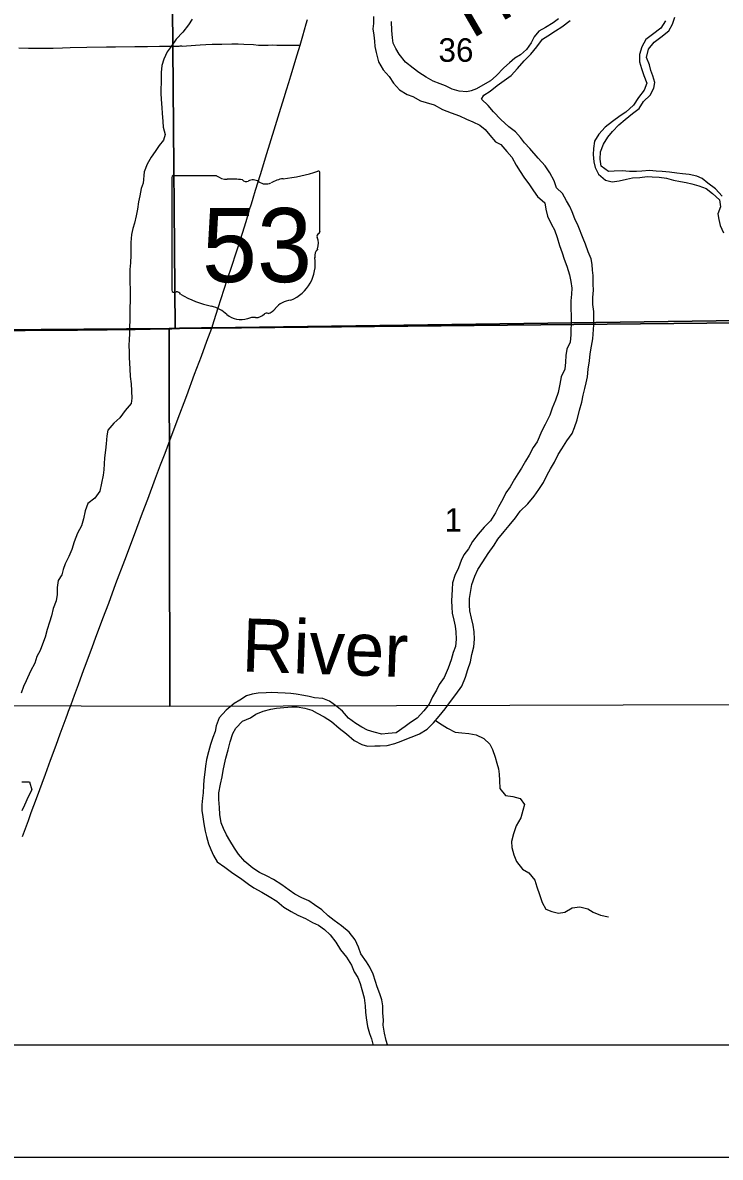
# Model space of a CAD drawing. Extents: x 0 to 34, y 0 to 22.
# Drawn here: x 3.064 to 3.685, y 14 to 15.009 of the extents above; entities that cross this region are included whole.
import ezdxf

# ---------------------------------------------------------------- set-up
doc = ezdxf.new("R2010")
doc.units = 0
for name, color, linetype in [('GM_X_Corporation', 7, 'Continuous'), ('GM_X_County_Road', 7, 'Continuous'), ('GM_X_Major_River', 7, 'Continuous'), ('GM_X_Major_River_Text', 7, 'Continuous'), ('GM_X_Minor_River', 7, 'Continuous'), ('GM_X_Section_Text', 7, 'Continuous'), ('GM_X_State_Location', 7, 'Continuous'), ('GM_X_State_Route', 7, 'Continuous'), ('GM_X_State_Shield', 7, 'Continuous'), ('GM_X_Township_Road', 7, 'Continuous'), ('SH_Data', 7, 'Continuous')]:
    doc.layers.add(name, color=color, linetype=linetype)

msp = doc.modelspace()

# ---------------------------------------------------------------- linework, layer by layer
at = {"layer": 'GM_X_Corporation'}
for points in [[(2.1, 20.7197), (2.1, 14.1), (8.9, 14.1), (8.9, 20.772)], [(3.7029, 14.7443), (3.2322, 14.7378), (3.2232, 14.7378), (3.2036, 14.7375), (3.1968, 14.7374), (3.1775, 14.737), (3.1641, 14.7368), (3.139, 14.7364), (3.1125, 14.7362), (3.0986, 14.7361), (3.0824, 14.736), (3.0715, 14.736), (3.066, 14.7359), (3.0551, 14.7357)], [(3.0551, 14.7357), (3.066, 14.7359), (3.0715, 14.736), (3.0824, 14.736), (3.0986, 14.7361), (3.1125, 14.7362), (3.139, 14.7364), (3.1641, 14.7368), (3.1775, 14.737), (3.1968, 14.7374), (3.2036, 14.7375), (3.2232, 14.7378), (3.2322, 14.7378), (3.7029, 14.7443)], [(2.1, 14.1), (3.6981, 14.1)]]:
    msp.add_lwpolyline(points, dxfattribs=at)
for points in [[(3.1955, 15.238), (3.7037, 15.2451), (3.7028, 14.7423), (3.1999, 14.7374)], [(2.7015, 15.236), (3.1955, 15.238), (3.1999, 14.7374), (3.1944, 14.7372), (2.7002, 14.7334)], [(2.7002, 14.7334), (3.1944, 14.7372), (3.1951, 14.4011), (2.8002, 14.4026), (2.7985, 14.2218), (2.6928, 14.2232), (2.6964, 14.7334)], [(3.1999, 14.7374), (3.7028, 14.7423), (3.6996, 14.4024), (3.1951, 14.4011), (3.1944, 14.7372)]]:
    msp.add_lwpolyline(points, close=True, dxfattribs=at)
at = {"layer": 'GM_X_County_Road'}
msp.add_lwpolyline([(3.0606, 14.9868), (3.0693, 14.9867), (3.0752, 14.9866), (3.0857, 14.9866), (3.0913, 14.9867), (3.0994, 14.9869), (3.1062, 14.9871), (3.1211, 14.9874), (3.1385, 14.9878), (3.1466, 14.9879), (3.164, 14.988), (3.1752, 14.9881), (3.1857, 14.9883), (3.1898, 14.9883), (3.1956, 14.9884), (3.2006, 14.9885), (3.2033, 14.9885), (3.2043, 14.9886), (3.2054, 14.9886), (3.2061, 14.9885), (3.2099, 14.9887), (3.222, 14.9896), (3.2272, 14.9899), (3.2328, 14.9901), (3.2412, 14.9903), (3.2502, 14.9905), (3.2558, 14.9905), (3.2608, 14.9903), (3.2695, 14.9898), (3.2741, 14.9894), (3.2816, 14.9893), (3.2825, 14.9893), (3.2865, 14.9895), (3.2902, 14.9894), (3.2952, 14.9893), (3.2968, 14.9893), (3.3027, 14.9893), (3.3064, 14.9893), (3.3073, 14.9893), (3.311, 14.9892)], dxfattribs=at)
at = {"layer": 'GM_X_Major_River'}
for points in [[(3.3764, 15.0149), (3.3765, 15.0087), (3.3759, 15.0039), (3.3766, 14.9981), (3.3772, 14.9929), (3.3775, 14.9882), (3.3786, 14.9827), (3.3808, 14.9745), (3.385, 14.9674), (3.3902, 14.9615), (3.3942, 14.9556), (3.3994, 14.9495), (3.4064, 14.9455), (3.4113, 14.9435), (3.4181, 14.9397), (3.4233, 14.9383)], [(3.3961, 14.9863), (3.394, 14.9911), (3.3933, 14.9958), (3.3926, 15.0023), (3.3925, 15.0103)], [(3.5411, 15.0126), (3.5363, 15.0092), (3.5296, 15.0051), (3.5235, 15.0017), (3.5195, 14.9968), (3.5168, 14.9915), (3.5126, 14.9853), (3.5072, 14.9808), (3.5023, 14.9778), (3.4975, 14.9736), (3.4925, 14.9691), (3.4857, 14.9621), (3.4805, 14.9576), (3.4757, 14.9548), (3.4681, 14.9505), (3.4634, 14.9488)], [(3.4747, 14.9448), (3.4802, 14.9485), (3.4865, 14.9534), (3.4988, 14.9624), (3.5045, 14.9686), (3.5104, 14.9754), (3.5163, 14.9813), (3.5219, 14.9877), (3.5267, 14.9945), (3.5316, 14.9975), (3.5385, 15.002), (3.544, 15.0057), (3.5515, 15.0113)], [(3.6363, 15.0109), (3.6321, 15.0043), (3.6248, 14.9988), (3.6189, 14.9943), (3.6152, 14.9879), (3.6131, 14.9811), (3.6131, 14.9746), (3.6151, 14.9684), (3.6171, 14.9623), (3.6198, 14.9556), (3.6174, 14.9494), (3.6124, 14.9428), (3.6078, 14.936), (3.601, 14.9298), (3.596, 14.9264), (3.5891, 14.9213), (3.5827, 14.9164), (3.5771, 14.91), (3.5731, 14.904), (3.5721, 14.8975), (3.572, 14.892), (3.5726, 14.8856), (3.5737, 14.8806), (3.5767, 14.8745), (3.5829, 14.8692), (3.5888, 14.8678), (3.5952, 14.8687), (3.6015, 14.8702), (3.607, 14.8713), (3.6134, 14.8716), (3.6199, 14.8725), (3.6246, 14.8723), (3.6307, 14.8719), (3.6372, 14.8709), (3.6434, 14.8693), (3.6498, 14.8681), (3.6548, 14.8671), (3.6599, 14.8658), (3.6661, 14.8642), (3.6724, 14.8617), (3.6782, 14.8573), (3.6843, 14.8517), (3.6854, 14.8455), (3.683, 14.8394), (3.6838, 14.8341), (3.6849, 14.8288), (3.688, 14.8225)], [(3.6869, 14.8549), (3.6807, 14.8614), (3.6739, 14.8666), (3.669, 14.8706), (3.6641, 14.8729), (3.6575, 14.8741), (3.6514, 14.8747), (3.6465, 14.8753), (3.6399, 14.8763), (3.6334, 14.877), (3.6281, 14.8772), (3.6222, 14.8778), (3.6152, 14.8771), (3.6105, 14.8769), (3.6042, 14.877), (3.5976, 14.8774), (3.5905, 14.8771), (3.5856, 14.8768), (3.579, 14.8816), (3.5783, 14.8878), (3.5785, 14.8945), (3.581, 14.9013), (3.5849, 14.9075), (3.5891, 14.9126), (3.5948, 14.9184), (3.6005, 14.9233), (3.6068, 14.9286), (3.6129, 14.9329), (3.6168, 14.9391), (3.6227, 14.9448), (3.626, 14.951), (3.6268, 14.9561), (3.6251, 14.962), (3.6232, 14.9668), (3.622, 14.9717), (3.6195, 14.9784), (3.6213, 14.9858), (3.6263, 14.992), (3.6322, 14.9965), (3.6393, 15.002), (3.6425, 15.008), (3.6447, 15.0141)], [(3.4634, 14.9488), (3.4595, 14.9479), (3.4527, 14.9483), (3.4463, 14.9501), (3.4406, 14.9532), (3.4357, 14.9549), (3.4295, 14.9572), (3.4232, 14.9609), (3.4168, 14.9649), (3.4117, 14.9688), (3.4047, 14.9741), (3.3991, 14.9812), (3.3961, 14.9863)], [(3.3659, 14.3673), (3.3709, 14.3658), (3.3775, 14.3661), (3.3822, 14.3661), (3.3885, 14.3664), (3.3952, 14.3682), (3.4009, 14.3703), (3.4075, 14.3729), (3.4123, 14.3746), (3.4172, 14.3766), (3.4241, 14.3807), (3.4298, 14.3866), (3.4348, 14.3924), (3.4402, 14.3988), (3.4448, 14.4056), (3.4496, 14.4117), (3.4549, 14.4192), (3.4582, 14.427), (3.4602, 14.4338), (3.4627, 14.4408), (3.4639, 14.4472), (3.4656, 14.4542), (3.4662, 14.4609), (3.4659, 14.4675), (3.4652, 14.4734), (3.4637, 14.4795), (3.4622, 14.4861), (3.4617, 14.4912), (3.4618, 14.4971), (3.4626, 14.5024), (3.4639, 14.5094), (3.4665, 14.517), (3.4692, 14.5229), (3.4738, 14.5297), (3.4784, 14.5372), (3.4837, 14.5446), (3.487, 14.55), (3.4927, 14.5568), (3.497, 14.5621), (3.5029, 14.5689), (3.5069, 14.5749), (3.5138, 14.5813), (3.5193, 14.5881), (3.5236, 14.594), (3.5278, 14.6004), (3.5311, 14.6072), (3.5339, 14.6125), (3.5376, 14.6185), (3.5407, 14.6253), (3.5441, 14.6302), (3.5484, 14.6374), (3.5532, 14.644), (3.5553, 14.6493), (3.5576, 14.6561), (3.5598, 14.6645), (3.5619, 14.6717), (3.5629, 14.6779), (3.5646, 14.684), (3.5656, 14.6889), (3.5668, 14.6944), (3.5674, 14.701), (3.5688, 14.7084), (3.5694, 14.7147), (3.5704, 14.7215), (3.5716, 14.7281), (3.5726, 14.7404), (3.5725, 14.7469), (3.5724, 14.7524), (3.5716, 14.7585), (3.5717, 14.7649), (3.5721, 14.7714), (3.572, 14.7767), (3.5718, 14.7843), (3.5713, 14.789), (3.5711, 14.7941), (3.5702, 14.7993), (3.5676, 14.8056), (3.5652, 14.8122), (3.563, 14.8172), (3.5585, 14.8286), (3.5555, 14.8349), (3.5533, 14.841), (3.5512, 14.8457), (3.5482, 14.8507), (3.5445, 14.8573), (3.5394, 14.8625), (3.5373, 14.8686), (3.5334, 14.8756), (3.5291, 14.8821), (3.5231, 14.8888), (3.5154, 14.8974), (3.5108, 14.9024), (3.5073, 14.9073), (3.5028, 14.9123), (3.4967, 14.9167), (3.4896, 14.9232), (3.4833, 14.9299), (3.4783, 14.9356), (3.4726, 14.9412), (3.4747, 14.9448)], [(3.4233, 14.9383), (3.4303, 14.9362), (3.4378, 14.9321), (3.4454, 14.929), (3.453, 14.9263), (3.4592, 14.9234), (3.4649, 14.9211), (3.4709, 14.9182), (3.4758, 14.9142), (3.4798, 14.9092), (3.4849, 14.9033), (3.4898, 14.9008), (3.4952, 14.8947), (3.4996, 14.8897), (3.5033, 14.8825), (3.5069, 14.8768), (3.5102, 14.872), (3.5151, 14.8651), (3.5187, 14.8598), (3.5223, 14.8547), (3.5289, 14.8489), (3.5299, 14.8434), (3.5314, 14.8371), (3.5348, 14.8299), (3.5374, 14.8251), (3.5398, 14.8181), (3.5419, 14.8111), (3.5443, 14.8046), (3.5461, 14.7989), (3.5486, 14.7926), (3.551, 14.785), (3.5519, 14.7791), (3.5528, 14.773), (3.5527, 14.7677), (3.5521, 14.7618), (3.5519, 14.7544), (3.5522, 14.7491), (3.5523, 14.7412), (3.5519, 14.7364), (3.5519, 14.7317), (3.5513, 14.725), (3.5484, 14.719), (3.5476, 14.7133), (3.5474, 14.7074), (3.5466, 14.7012), (3.5433, 14.6942), (3.5421, 14.6876), (3.5407, 14.6804), (3.5384, 14.6735), (3.5355, 14.6665), (3.5332, 14.6601), (3.5291, 14.652), (3.5262, 14.6461), (3.522, 14.6363), (3.5185, 14.6314), (3.5149, 14.6246), (3.5118, 14.6193), (3.508, 14.6129), (3.5049, 14.608), (3.502, 14.6031), (3.498, 14.5963), (3.4943, 14.591), (3.4916, 14.5855), (3.4876, 14.5787), (3.4851, 14.5732), (3.4805, 14.5662), (3.4749, 14.5604), (3.4696, 14.5544), (3.4644, 14.5479), (3.4608, 14.5413), (3.4569, 14.5359), (3.4544, 14.5308), (3.4521, 14.5243), (3.4488, 14.5175), (3.4467, 14.5111), (3.4464, 14.505), (3.4462, 14.5001), (3.4458, 14.495), (3.4461, 14.4893), (3.4465, 14.4841), (3.448, 14.4779), (3.4491, 14.4726), (3.4498, 14.4674), (3.4501, 14.4608), (3.4493, 14.4543), (3.4474, 14.4489), (3.4454, 14.4426), (3.4429, 14.4352), (3.4394, 14.4267), (3.4348, 14.4207), (3.4325, 14.4156), (3.429, 14.4095), (3.4258, 14.4031), (3.4212, 14.3971), (3.4152, 14.3907), (3.4093, 14.3867), (3.4044, 14.3832), (3.3964, 14.3777), (3.3893, 14.377), (3.3838, 14.3765), (3.3768, 14.3781)], [(3.3768, 14.3781), (3.371, 14.38), (3.366, 14.3827), (3.3606, 14.3858), (3.354, 14.3907), (3.3487, 14.397), (3.3438, 14.4009), (3.3372, 14.4057), (3.3311, 14.408), (3.3239, 14.4088), (3.319, 14.41), (3.3143, 14.4108), (3.3074, 14.412), (3.3027, 14.4126), (3.2978, 14.413), (3.2913, 14.4132), (3.2855, 14.4136), (3.2807, 14.4131), (3.2737, 14.4128), (3.2682, 14.4119), (3.2634, 14.4106), (3.2573, 14.4066), (3.2524, 14.4037), (3.2453, 14.3978), (3.239, 14.3909), (3.2363, 14.3839), (3.2353, 14.3789), (3.2334, 14.3733), (3.2312, 14.3672), (3.2295, 14.3608), (3.2277, 14.3539), (3.2269, 14.3479), (3.2261, 14.3426), (3.2253, 14.3358), (3.2251, 14.3306), (3.2248, 14.3242), (3.2242, 14.3194), (3.2236, 14.3136), (3.2236, 14.3085), (3.2245, 14.3029), (3.2254, 14.2967), (3.2265, 14.2902), (3.2276, 14.2853), (3.2294, 14.2788), (3.2315, 14.2737), (3.2339, 14.2685), (3.2373, 14.2628), (3.2439, 14.258), (3.2512, 14.2527), (3.2579, 14.2484), (3.265, 14.2429), (3.2699, 14.2396), (3.2769, 14.236), (3.2835, 14.2321), (3.2903, 14.2279), (3.2966, 14.2224), (3.303, 14.2187), (3.309, 14.2154), (3.3158, 14.2123), (3.3221, 14.2089), (3.3274, 14.2064), (3.3328, 14.2025), (3.3379, 14.1978), (3.3428, 14.1913), (3.3469, 14.1846), (3.3522, 14.1779), (3.3567, 14.1709), (3.3591, 14.165), (3.3623, 14.16), (3.3644, 14.1545), (3.366, 14.1494), (3.3679, 14.142), (3.3688, 14.1347), (3.3693, 14.1292), (3.3698, 14.1241), (3.3711, 14.1163), (3.3729, 14.1102), (3.3746, 14.1055), (3.3757, 14.1005), (3.3758, 14.1)], [(3.3887, 14.1), (3.3877, 14.1039), (3.3862, 14.1103), (3.3851, 14.1174), (3.3852, 14.1221), (3.3848, 14.1285), (3.3847, 14.1346), (3.3838, 14.1401), (3.3819, 14.1453), (3.3795, 14.1517), (3.3782, 14.1565), (3.3762, 14.1629), (3.373, 14.1692), (3.3702, 14.174), (3.3651, 14.1809), (3.3629, 14.1869), (3.3599, 14.1934), (3.3546, 14.2003), (3.348, 14.206), (3.3412, 14.2106), (3.336, 14.2147), (3.3303, 14.2202), (3.3239, 14.2246), (3.3188, 14.2281), (3.3126, 14.2308), (3.3063, 14.2342), (3.3012, 14.2377), (3.2946, 14.2423), (3.2874, 14.2471), (3.2818, 14.2502), (3.2748, 14.2534), (3.2689, 14.2571), (3.2619, 14.2632), (3.2561, 14.2697), (3.2526, 14.275), (3.2484, 14.2819), (3.2454, 14.287), (3.2428, 14.2926), (3.2406, 14.2975), (3.2395, 14.3049), (3.2392, 14.3112), (3.2386, 14.3184), (3.2387, 14.3243), (3.2401, 14.3318), (3.2416, 14.3383), (3.2424, 14.3442), (3.2436, 14.3498), (3.245, 14.3551), (3.2469, 14.3625), (3.2487, 14.3695), (3.2512, 14.3769), (3.2537, 14.3818), (3.2596, 14.3879), (3.2667, 14.391), (3.2715, 14.3942), (3.2781, 14.397), (3.285, 14.3987), (3.2899, 14.3994), (3.2964, 14.4001), (3.3036, 14.4008), (3.3083, 14.4006), (3.3151, 14.3996), (3.3214, 14.3978), (3.3263, 14.3951), (3.3325, 14.3917), (3.3391, 14.3876), (3.3459, 14.3817), (3.3523, 14.3767), (3.3591, 14.3708), (3.3659, 14.3673)]]:
    msp.add_lwpolyline(points, dxfattribs=at)
at = {"layer": 'GM_X_Minor_River'}
for points in [[(3.2149, 15.0124), (3.2116, 15.0075), (3.2065, 15.0009), (3.2007, 14.9946), (3.1961, 14.9882), (3.1927, 14.9833), (3.1896, 14.9767), (3.188, 14.9712), (3.1874, 14.9651), (3.1874, 14.9598), (3.1869, 14.9462), (3.1873, 14.9414), (3.1878, 14.9336), (3.1881, 14.9287), (3.1888, 14.9215), (3.1892, 14.9164), (3.1908, 14.9099), (3.1893, 14.9048), (3.1854, 14.8999), (3.182, 14.8948), (3.1785, 14.8897), (3.1747, 14.8835), (3.1722, 14.8765), (3.1713, 14.8666), (3.1696, 14.8617), (3.1682, 14.8552), (3.167, 14.8499), (3.1661, 14.8433), (3.1651, 14.8376), (3.1637, 14.831), (3.1621, 14.8261), (3.1608, 14.8208), (3.1603, 14.8137), (3.1603, 14.8086), (3.1604, 14.8024), (3.16, 14.7957), (3.1594, 14.7898), (3.1594, 14.7834), (3.1595, 14.7785), (3.1596, 14.772), (3.1595, 14.7456), (3.1592, 14.7375), (3.159, 14.7327), (3.1587, 14.7271), (3.1585, 14.7223), (3.1587, 14.7162), (3.1588, 14.7115)], [(3.1588, 14.7115), (3.1592, 14.7064), (3.1595, 14.7014), (3.1598, 14.6946), (3.1606, 14.688), (3.1612, 14.6754), (3.1606, 14.6705), (3.1554, 14.6643), (3.1505, 14.6579), (3.1453, 14.653), (3.1399, 14.6469), (3.139, 14.6418), (3.1382, 14.6348), (3.1377, 14.6291), (3.1369, 14.6223), (3.1365, 14.6168), (3.1363, 14.6115), (3.1357, 14.6068), (3.1341, 14.5996), (3.1327, 14.5925), (3.1283, 14.5863), (3.122, 14.5816), (3.1197, 14.575), (3.1183, 14.5678), (3.1164, 14.5617), (3.1127, 14.5553), (3.1098, 14.5474), (3.1077, 14.5406), (3.105, 14.5343), (3.1019, 14.5279), (3.1001, 14.523), (3.099, 14.5181), (3.0955, 14.513), (3.0947, 14.5069), (3.0947, 14.5006), (3.0937, 14.4951), (3.0913, 14.4883), (3.0896, 14.4817), (3.088, 14.476), (3.0859, 14.4696), (3.0841, 14.4628), (3.0818, 14.4565), (3.0797, 14.4507), (3.0766, 14.4456), (3.0749, 14.4397), (3.071, 14.4323), (3.067, 14.4238), (3.0648, 14.4187), (3.0627, 14.4129)], [(3.4317, 14.3887), (3.4374, 14.3848), (3.4423, 14.3817), (3.4491, 14.3783), (3.455, 14.3777), (3.4611, 14.377), (3.4677, 14.3759), (3.4747, 14.3724), (3.4798, 14.3676), (3.4824, 14.3628), (3.4846, 14.3558), (3.4863, 14.3507), (3.4876, 14.3457), (3.4883, 14.3408), (3.4886, 14.3353), (3.4888, 14.3281), (3.4939, 14.3218), (3.5003, 14.321), (3.5069, 14.3192), (3.5107, 14.3139), (3.5093, 14.3084), (3.5074, 14.302), (3.5035, 14.2948), (3.501, 14.2878), (3.4991, 14.2808), (3.4994, 14.2756), (3.5014, 14.269), (3.5037, 14.2631), (3.5089, 14.2564), (3.5146, 14.253), (3.5199, 14.2465), (3.5217, 14.2406), (3.5241, 14.2339), (3.5264, 14.2267), (3.5297, 14.2208), (3.535, 14.2187), (3.5411, 14.2173), (3.5468, 14.2182), (3.5533, 14.2219), (3.5601, 14.2228), (3.5671, 14.2211), (3.572, 14.218), (3.5784, 14.2153), (3.5855, 14.2139)], [(3.0633, 14.3339), (3.0701, 14.3339), (3.0721, 14.327), (3.0689, 14.3208), (3.0656, 14.3132), (3.0634, 14.3081)]]:
    msp.add_lwpolyline(points, dxfattribs=at)
at = {"layer": 'GM_X_State_Route'}
for points in [[(3.311, 14.9892), (3.3134, 14.9976), (3.3149, 15.0028), (3.3165, 15.0084), (3.3175, 15.012)], [(3.2323, 14.7375), (3.2344, 14.7444), (3.2382, 14.7556), (3.2462, 14.7804), (3.2504, 14.7935), (3.2537, 14.8038), (3.2564, 14.8117), (3.2596, 14.8221), (3.2629, 14.8324), (3.2657, 14.8417), (3.2661, 14.8431), (3.2678, 14.8482), (3.2693, 14.8532), (3.2714, 14.8604), (3.2758, 14.8743), (3.2815, 14.893), (3.288, 14.9141), (3.2891, 14.9177), (3.2926, 14.9293), (3.2968, 14.9426), (3.2989, 14.9495), (3.3009, 14.956), (3.3027, 14.9619), (3.3085, 14.9806), (3.311, 14.9892)], [(3.0639, 14.2854), (3.0692, 14.2997), (3.0717, 14.3067), (3.0763, 14.3192), (3.0843, 14.3408), (3.0889, 14.3533), (3.0937, 14.3665), (3.0975, 14.3767), (3.1027, 14.391), (3.1039, 14.3942), (3.1049, 14.3968), (3.1066, 14.4014), (3.1071, 14.4029), (3.1101, 14.4111), (3.1136, 14.4207), (3.1185, 14.4338), (3.119, 14.4353), (3.1231, 14.4463), (3.1261, 14.4545), (3.1289, 14.4617), (3.1354, 14.4792), (3.1406, 14.4929), (3.147, 14.5104), (3.155, 14.5313), (3.159, 14.5421), (3.1656, 14.5595), (3.1707, 14.5732), (3.1753, 14.5854), (3.1822, 14.604), (3.1867, 14.616), (3.1908, 14.6264), (3.1949, 14.6375), (3.2015, 14.6552), (3.2101, 14.6776), (3.2171, 14.6965), (3.2231, 14.7125), (3.2281, 14.7259), (3.2323, 14.7375)]]:
    msp.add_lwpolyline(points, dxfattribs=at)
at = {"layer": 'GM_X_State_Shield'}
for p, q in [((3.1968, 14.8715), (3.1968, 14.7714)), ((3.2367, 14.8732), (3.1981, 14.8732)), ((3.3286, 14.8233), (3.3286, 14.8757)), ((3.3286, 14.8234), (3.3286, 14.8233))]:
    msp.add_line(p, q, dxfattribs=at)
for centre, radius, start, end in [((3.2816, 15.0096), 0.1398, 275.8445, 288.9065), ((3.3271, 14.8759), 0.00147, 351.8621, 97.738), ((3.1983, 14.8717), 0.00153, 98.1301, 188.1301), ((3.2459, 14.8848), 0.0148, 231.6195, 271.1119), ((3.2508, 14.817), 0.0532, 80.4867, 94.9883), ((3.2629, 14.8722), 0.00427, 219.7921, 297.1024), ((3.2691, 14.8606), 0.00889, 54.4667, 119.1411), ((3.2806, 14.8765), 0.0107, 233.8562, 294.8282), ((3.2995, 14.8426), 0.0281, 97.3462, 120.7689), ((3.3283, 14.8195), 0.00227, 107.944, 210.337), ((3.3138, 14.8129), 0.0136, 340.033, 23.6496), ((3.327, 14.8231), 0.00157, 289.6038, 7.7341), ((3.3339, 14.8014), 0.00992, 136.8065, 186.9296), ((3.2895, 14.7948), 0.035, 292.3089, 8.9858), ((3.1983, 14.7712), 0.00154, 171.9584, 258.3066), ((3.1985, 14.7814), 0.0118, 267.339, 280.6039), ((3.2009, 14.7656), 0.00424, 29.7484, 93.2717), ((3.2545, 14.8555), 0.101, 240.4129, 257.1985), ((3.2244, 14.7265), 0.0316, 47.1842, 75.836), ((3.3042, 14.7433), 0.0192, 94.4031, 142.5768), ((3.2585, 14.7652), 0.02, 230.7004, 286.2918), ((3.2701, 14.7306), 0.0165, 85.6951, 111.2099), ((3.2716, 14.7577), 0.0107, 268.777, 315.5493), ((3.2812, 14.748), 0.00301, 65.7517, 132.6484), ((3.28, 14.7617), 0.0113, 282.8732, 323.2771)]:
    msp.add_arc(centre, radius, start, end, dxfattribs=at)
at = {"layer": 'GM_X_Township_Road'}
msp.add_lwpolyline([(3.0552, 14.7355), (3.0661, 14.7356), (3.0717, 14.7357), (3.0825, 14.7357), (3.0987, 14.7358), (3.1127, 14.7359), (3.1391, 14.7361), (3.1642, 14.7365), (3.1776, 14.7367), (3.1969, 14.7371), (3.2037, 14.7372), (3.2233, 14.7375), (3.2323, 14.7375)], dxfattribs=at)
at = {"layer": 'SH_Data'}
for p, q in [((2.1, 14.1), (8.9, 14.1)), ((2, 14), (9, 14))]:
    msp.add_line(p, q, dxfattribs=at)

# ---------------------------------------------------------------- texts
at = {"layer": 'GM_X_Major_River_Text'}
for s, rotation, p in [('Honey', 30.2258, (3.4639, 14.9945)), ('River', 358.0157, (3.2586, 14.4322))]:
    msp.add_text(s, height=0.04737, rotation=rotation, dxfattribs=at).set_placement(p)
at = {"layer": 'GM_X_Section_Text'}
for s, height, p in [('36', 0.02093, (3.4342, 14.9745)), ('1', 0.0209, (3.4396, 14.5565))]:
    msp.add_text(s, height=height, rotation=0, dxfattribs=at).set_placement(p)
at = {"layer": 'GM_X_State_Location'}
msp.add_text('53', height=0.0000947, rotation=0, dxfattribs=at).set_placement((3.2374, 14.8079))
for s in ['s', 'r']:
    msp.add_text(s, height=0.0000947, dxfattribs=at).set_placement((3.2612, 14.8148))
at = {"layer": 'GM_X_State_Shield'}
msp.add_text('53', height=0.06592, dxfattribs=at).set_placement((3.2236, 14.7785))

doc.saveas('drawing.dxf')
